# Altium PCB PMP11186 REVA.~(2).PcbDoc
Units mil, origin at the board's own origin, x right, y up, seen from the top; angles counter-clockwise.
Board outline 4950 x 3450 mil, 2 copper layers (Top Layer, Bottom Layer), stack 62 mil thick; 91 components, 38 nets, 225 pads, 56 vias.
Unrouted connection lines stored in the file: 161.
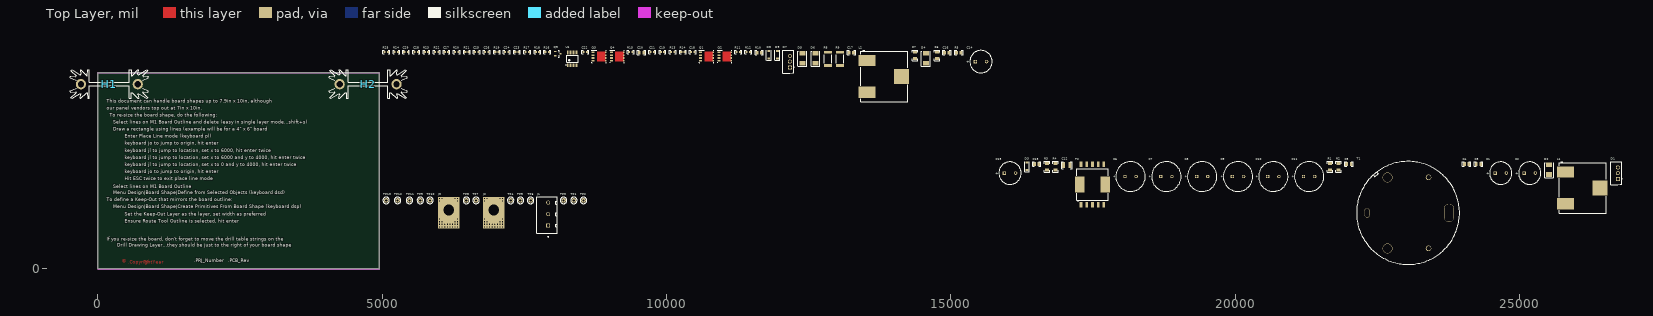
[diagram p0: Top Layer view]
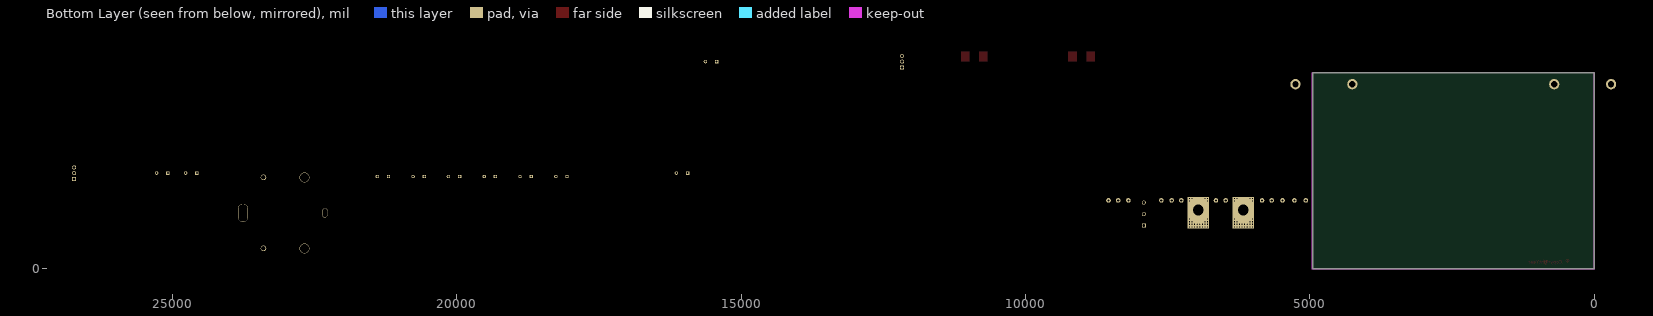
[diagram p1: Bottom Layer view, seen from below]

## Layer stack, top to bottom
Top Solder: solder mask 0.4, Solder Resist, Dk 3.5
Top Layer: signal copper 1.4
Dielectric1: core 59.2, FR-4, Dk 4.8
Bottom Layer: signal copper 1.4
Bottom Solder: solder mask 0.4, Solder Resist, Dk 3.5

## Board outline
0,0 4950,0 4950,3450 0,3450

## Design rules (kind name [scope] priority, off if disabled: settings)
AcuteAngle [All] p1: minimum=4.50000000000000E+0001 checktracksonly=FALSE
AssemblyTestPointUsage [All] p1: valid=2
Clearance Clearance_Keepouts [((IsTrack Or IsArc) And Not InPoly) And IsFree and IsKeepOut vs ((IsTrack Or IsArc) And Not InPoly) And IsFree and IsKeepOut] p1: gap=0
Clearance Clearance_BoardEdge_MountingHoles [OnCopper and InComponentClass('Mounting Holes') vs IsKeepOut] p2: gap=40
Clearance Clearance_BoardEdge_Poly [OnCopper and InPoly vs IsKeepOut] p3: gap=25
Clearance Clearance_BoardEdge [OnCopper and Not InComponentClass('Logo') and not InComponentClass('FiducialMark') and not InRegion(1000,500,4000,800) and Not IsKeepout vs IsKeepOut] p4: gap=75
Clearance Clearance_Poly [InPolygon] p5: gap=25
Clearance [All] p6: gap=7.87
ComponentClearance ComponentClearance_MountingHoles_FiducialMarks [InComponentClass('Mounting Holes') vs InComponentClass('FiducialMark')] p1: gap=50 collisioncheckmode=3 verticalgap=10 showdistances=FALSE
ComponentClearance ComponentClearance_Shunt [InComponentClass('Header') vs InComponentClass('Shunt')] p2: gap=0 collisioncheckmode=3 verticalgap=0 showdistances=FALSE
ComponentClearance ComponentClearance_Logo [InComponentClass('Logo')] p3: gap=50 collisioncheckmode=3 verticalgap=10 showdistances=FALSE
ComponentClearance ComponentClearance_ScrewToNut [(HasFootprint('NY PMS 440 0025 PH')) vs (HasFootprint('Keystone_1902C'))] p4: gap=5 collisioncheckmode=3 verticalgap=10 showdistances=FALSE
ComponentClearance ComponentClearance_MountingHoles [InComponentClass('Mounting Holes')] p5: gap=250 collisioncheckmode=3 verticalgap=100000 showdistances=FALSE
ComponentClearance ComponentClearance_SmallPassives [HasFootprint('0201*') or HasFootprint('0402*') or HasFootprint('0508') or HasFootprint('0603*') or HasFootprint('0612') or HasFootprint('0805*') or HasFootprint('0815*') or HasFootprint('0830*') or HasFootprint('1206*') or HasFootprint('1210*') or HasFootprint('1808*') or HasFootprint('1812*') or HasFootprint('1825*') or HasFootprint('2010*') or HasFootprint('2220*') or HasFootprint('2225*') or HasFootprint('2512*') or HasFootprint('2728*') or HasFootprint('3518*') vs HasFootprint('0201*') or HasFootprint('0402*') or HasFootprint('0508') or HasFootprint('0603*') or HasFootprint('0612') or HasFootprint('0805*') or HasFootprint('0815*') or HasFootprint('0830*') or HasFootprint('1206*') or HasFootprint('1210*') or HasFootprint('1808*') or HasFootprint('1812*') or HasFootprint('1825*') or HasFootprint('2010*') or HasFootprint('2220*') or HasFootprint('2225*') or HasFootprint('2512*') or HasFootprint('2728*') or HasFootprint('3518*')] p6: gap=20 collisioncheckmode=3 verticalgap=10 showdistances=FALSE
ComponentClearance ComponentClearance_THtoSMT [IsThruComponent vs IsSMTComponent] p7: gap=100 collisioncheckmode=3 verticalgap=30 showdistances=FALSE
ComponentClearance ComponentClearance_THtoTH [IsThruComponent vs IsThruComponent] p8: gap=118.11 collisioncheckmode=3 verticalgap=30 showdistances=FALSE
ComponentClearance [All] p9: gap=40 collisioncheckmode=3 verticalgap=10 showdistances=FALSE
DiffPairsRouting [All] p1: maxlimit=100 minlimit=10 mostfreqgap=10 toplayer_minwidth=15 toplayer_maxwidth=15 toplayer_prefwidth=15 bottomlayer_minwidth=15 bottomlayer_maxwidth=15 bottomlayer_prefwidth=15 maxuncoupledlength=1000
FabricationTestPointUsage TestPointUsage [All] p1: valid=2 allowmultiple=FALSE
FabricationTestpoint Testpoint [All] p1: side=3 testpointundercomponent=TRUE minsize=40 maxsize=100 preferedsize=60 minholesize=0 maxholesize=40 preferedholesize=32 testpointgrid=1 allowsidetop=TRUE allowsidebottom=TRUE usegrid=TRUE gridtolerance=0.01
FanoutControl Fanout_LCC [IsLCC] p1: bgadir=Out bgaviamode=Centered fanoutstyle=Auto fanoutdirection=Alternating viagrid=1 // Fanout_LCC (Default Rule)
FanoutControl Fanout_BGA [IsBGA] p2: bgadir=Out bgaviamode=Centered fanoutstyle=Auto fanoutdirection=Alternating viagrid=1 // Fanout_BGA (Default Rule)
FanoutControl Fanout_Default [All] p4: bgadir=Out bgaviamode=Centered fanoutstyle=Auto fanoutdirection=Alternating viagrid=1 // Fanout_Default (Default Rule)
FanoutControl Fanout_Small [(CompPinCount < 5)] p5: bgadir=Out bgaviamode=Centered fanoutstyle=Auto fanoutdirection=OutThenIn viagrid=1 // Fanout_Small (Default Rule)
HoleSize [All] p1: absolutevalues=TRUE maxlimit=251 minlimit=8 maxpercent=80.000 minpercent=20.000
MinimumAnnularRing MinimumAnnularRing_ThermalPadVias [IsVia and InAnyComponent] p1: minimumring=5.91
MinimumAnnularRing [All] p2: minimumring=9
MinimumSolderMaskSliver MinimumSolderMaskSliver_Logo [InComponentClass('Logo') vs InComponentClass('Logo')] p1: minsoldermaskwidth=0.7
MinimumSolderMaskSliver [All] p2: minsoldermaskwidth=3.94
PlaneConnect [All] p1: planeconnectstyle=Relief reliefexpansion=10 reliefentries=4 reliefconductorwidth=10 reliefairgap=10
PolygonConnect [All] p1: connectstyle=Relief reliefconductorwidth=10 reliefentries=4 polygonreliefangle="90 Angle" airgapwidth=10
RoutingVias ThermalPadVias [IsVia and InAnyComponent] p1: holewidth=7.87 width=19.68 viastyle="Through Hole" minholewidth=7.87 minwidth=19.68 maxholewidth=12.99 maxwidth=23.62
RoutingVias [All] p2: holewidth=16 width=34 viastyle="Through Hole" minholewidth=7.87 minwidth=26 maxholewidth=40 maxwidth=65
SilkToBoardRegionClearance [Not ((IsComment or IsDesignator) And (Hide <> 'False')) and not InRegion(1000,500,4000,800)] p1:
SilkToSilkClearance SilkToSilkClearance_Pb-FreeLogo [(HasFootprint('Pb-Free_Overlay_Medium') OR HasFootprint('Pb-Free_Overlay_Small')) vs (HasFootprint('Pb-Free_Overlay_Medium') OR HasFootprint('Pb-Free_Overlay_Small'))] p1: silktosilkclearance=0
SilkToSilkClearance [All] p2: silktosilkclearance=5
SilkToSolderMaskClearance "Silk to Solder Mask Opening" [All] p1: minsilkscreentomaskgap=1 clearancetoexposedcopper=FALSE
SolderMaskExpansion [All] p1: expansion=1.97
UnpouredPolygon [All] p1: allowunpoured=FALSE
Width [All] p1: maxlimit=100 minlimit=6 preferedwidth=10 checkconnectedcopper=TRUE
14 further rules are at their usual default settings.

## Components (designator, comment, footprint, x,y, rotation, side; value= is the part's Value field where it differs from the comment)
C1 "35ZL470MEFC10X20" CAPPR5-10X20 24668,1686 r0 top
C2 "35ZL470MEFC10X20" CAPPR5-10X20 25178,1686 r0 top
C3 "GRM21BR71H105KA12L" 0805_HV 24278,1846 r0 top
C4 "GRM21A5C2E101JW01D" 0805_HV 24068,1846 r0 top
C5 "C2012X7R2A103M" 0805_HV 21998,1846 r0 top
C6 "25ZLH2700M12.5X35" ZLH_1250x2500 18158,1626 r0 top
C7 "25ZLH2700M12.5X35" ZLH_1250x2500 18788,1626 r0 top
C8 "25ZLH2700M12.5X35" ZLH_1250x2500 19418,1626 r0 top
C9 "25ZLH2700M12.5X35" ZLH_1250x2500 20048,1626 r0 top
C10 "25ZLH2700M12.5X35" ZLH_1250x2500 20668,1626 r0 top
C11 "25ZLH2700M12.5X35" ZLH_1250x2500 21298,1626 r0 top
C12 "C3225X7R1E106M" 1210 17038,1826 r0 top
C13 "C2012X7R2A103M" 0805_HV 16508,1846 r0 top
C14 "35ZL470MEFC10X20" CAPPR5-10X20 15528,3646 r0 top
C15 "35ZL470MEFC10X20" CAPPR5-10X20 16038,1686 r0 top
C16 "GRM21BR71H105KA12L" 0805_HV 14928,3806 r0 top
C17 "C2012X7R2A103M" 0805_HV 13248,3806 r0 top
C18 "C1608C0G1H152J" 0603 10458,3816 r0 top
C19 "C1608C0G1H101J" 0603 9928,3816 r0 top
C20 "C2012X7R1E105K" 0805_HV 9558,3806 r0 top
C21 "" 0603 9748,3816 r0 top
C22 "C1608X7R1C105K" 0603 8568,3816 r0 top
C23 "C1608X7R1H473K" 0603 7368,3816 r0 top
C24 "C1608C0G1H150J" 0603 7188,3816 r0 top
C25 "C1608X7R1C105K" 0603 6658,3816 r0 top
C26 "C1608X7R1H103K" 0603 6838,3816 r0 top
C27 "" 0603 6128,3816 r0 top
C28 "C1608X7R1C105K" 0603 5598,3816 r0 top
C29 "C1608C0G1H101J" 0603 5418,3816 r0 top
D1 "FML22S" ITO-220AB 26728,1686 r90 top
D2 "MURS120-13-F" SMB 25518,1746 r90 top
D3 "MMSD4148T1G" SOD-123 16338,1806 r90 top
D4 "MURS120-13-F" SMB 14558,3706 r90 top
D5 "MURS120-13-F" SMB 12388,3706 r90 top
D6 "MURS120-13-F" SMB 12618,3706 r90 top
D7 "FML22R" ITO-220AB 12168,3646 r90 top
D8 "BAT54T1G" SOD-123 11798,3766 r90 top
D9 "BAT54T1G" SOD-123 11948,3766 r90 top
H1 "513201B02500G" HSINK_513201B02500 200,3250 r0 top locked
H2 "513201B02500G" HSINK_513201B02500 4750,3250 r0 top locked
J1 "OSTTA034163" On-Shore_OSTTA034163 7898,946 r90 top
J2 "CB35-36-CY" CB35-36-CY 6958,1036 r90 top
J3 "CB35-36-CY" CB35-36-CY 6168,1036 r90 top
L1 "B82559A0353A020" B82559_1420 26108,1426 r0 top
L2 "B82559A0353A020" B82559_1420 13828,3386 r0 top
Q1 "DNP" TRANS_NexFET_Q5B 10708,3736 r0 top
Q2 "DNP" TRANS_NexFET_Q5B 11028,3736 r0 top
Q3 "CSD18540Q5B" TRANS_NexFET_Q5B 8818,3736 r0 top
Q4 "CSD18540Q5B" TRANS_NexFET_Q5B 9138,3736 r0 top
Q5 "2N7002P,215" SOT-23 8088,3786 r0 top
R1 "" 1206 21668,1796 r90 top
R2 "CRCW120649K9FKEA" 1206 21818,1796 r90 top
R3 "" 1206 16688,1796 r90 top
R4 "CRCW120649K9FKEA" 1206 16838,1796 r90 top
R5 "CRCW08051K00FKEA" 0805_HV 15138,3806 r0 top
R6 "CRCW1206100RFKEA" 1206 14758,3756 r90 top
R7 "CSR1206FKR750" 1206 14368,3756 r90 top
R8 "" 2512 12838,3696 r90 top
R9 "CRCW251210K0JNEG" 2512 13048,3696 r90 top
R10 "ERJ-6GEYJ4R7V" 0805_HV 11628,3806 r0 top
R11 "" 0603 11258,3816 r0 top
R12 "CRCW06031K00FKEA" 0603 11438,3816 r0 top
R13 "CRCW06031R00FKEA" 0603 10108,3816 r0 top
R14 "CRCW06031R00FKEA" 0603 10288,3816 r0 top
R15 "CRCW0603130KFKEA" 0603 9368,3816 r0 top
R16 "CRCW0603200KFKEA" 0603 7898,3816 r0 top
R17 "CRCW060310K0FKEA" 0603 7548,3816 r0 top
R18 "CRCW060321K0FKEA" 0603 7728,3816 r0 top
R19 "CRCW0603100KFKEA" 0603 7018,3816 r0 top
R20 "CRCW060347K5FKEA" 0603 6308,3816 r0 top
R21 "CRCW060349R9FKEA" 0603 6488,3816 r0 top
R22 "" 0603 5958,3816 r0 top
R23 "CRCW06032K49FKEA" 0603 5778,3816 r0 top
R24 "CRCW060349K9FKEA" 0603 5248,3816 r0 top
R25 "CRCW060329K4FKEA" 0603 5068,3816 r0 top
T1 "G154027ALF" GCI_G154027ALF 23038,986 r0 top
T2 "G154028ALF" GCI_G154028ALF 17488,1486 r90 top
TP1 "5000" Keystone5000 8368,1206 r0 top
TP2 "5000" Keystone5000 8538,1206 r0 top
TP3 "5000" Keystone5000 8188,1206 r0 top
TP4 "5000" Keystone5000 7258,1206 r0 top
TP5 "5001" Keystone5001 7428,1206 r0 top
TP6 "5001" Keystone5001 7608,1206 r0 top
TP7 "5000" Keystone5000 6648,1206 r0 top
TP8 "5001" Keystone5001 6478,1206 r0 top
TP9 "5000" Keystone5000 5668,1206 r0 top
TP10 "5000" Keystone5000 5838,1206 r0 top
TP11 "5000" Keystone5000 5478,1206 r0 top
TP12 "5000" Keystone5000 5268,1206 r0 top
TP13 "5000" Keystone5000 5068,1206 r0 top
U1 "LM25037QMT" MTC16_N 8348,3696 r90 top

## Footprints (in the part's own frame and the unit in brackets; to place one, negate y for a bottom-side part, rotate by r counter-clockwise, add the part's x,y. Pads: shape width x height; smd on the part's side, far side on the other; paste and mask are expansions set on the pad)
0603 [mm] "0603 from SM-752 data"
  rect 1x0.95 smd: 1(-0.8,0) 2(0.8,0)
  silkscreen extent -1.52,-0.69 1.52,0.69, body extent -0.87,-0.47 0.87,0.47, height 0.85
0805_HV [mil] "0805 with 30mil clearance between pads"
  rect 50x63 smd: 1(-40,0) 2(40,0)
  silkscreen extent -74,-40 74,40, body extent -43,-29 43,29, height 57
1206 [mm] "1206 from SM-752 data"
  rect 1.3x1.85 smd: 1(-1.45,0) 2(1.45,0)
  silkscreen extent -2.4,-1.21 2.4,1.21, body extent -1.7,-0.9 1.7,0.9, height 1.35
1210 [mm] "1210 from SM-752 data"
  rect 1.3x2.7 smd: 1(-1.45,0) 2(1.45,0)
  silkscreen extent -2.32,-1.57 2.32,1.57, body extent -1.7,-1.35 1.7,1.35, height 1.35
2512 [mm] "Chip Resistor, Body 6.3x3.2mm, IPC Medium Density"
  rect 1.3x3.4 smd: 1(-2.95,0) 2(2.95,0)
  silkscreen extent -1.9,-1.6 1.9,1.6, body extent -3.22,-1.67 3.22,1.67, height 0.71
B82559_1420 [mm] "SMD, 3-Leads, Body 21.5x21mm"
  rect 7.6x5 smd: 1(-7.675,7.1) 2(-7.675,-7.1)
  rect 6.7x6.8 smd: 3(7.675,0)
  silkscreen extent -10.5,-11.25 10.5,11.7, body extent -11,-11.25 11,11.25, height 14.2
CAPPR5-10X20 [mm] "Capacitor, Electrolytic, Radial; Body 10 x 20 mm (Dia.xH typ); Pin Spacing 5 mm (typ)"
  rect 1.5x1.5 hole 0.9: 1(-2.5,0)
  round 1.5 hole 0.9: 2(2.5,0)
  silkscreen extent -5,-5 5,5, body extent -5.01,-5.01 5.01,5.01, height 22
CB35-36-CY [mil] "Terminal 50A Lug"
  rect 550x380 hole 188 copper offset -45,0 paste-190: 1(0,0)
  body extent -960,-189 230,191, height 614
GCI_G154027ALF [mm] "TH, 6-Leads, Dia 46mm"
  round 4.4 hole 3.9: 1(-9.15,15.848) 3(-9.15,-15.848)
  oval 2.5x4.1 hole 2 slot 3.6 at 90 deg: 2(-18.3,0)
  round 2.5 hole 2: 4(9.15,-15.848) 6(9.15,15.848)
  oval 4.5x8.1 hole 4 slot 7.6 at 90 deg: 5(18.3,0)
  silkscreen extent -23,-23 23,23, body extent -23.01,-23.01 23.01,23.01, height 28
GCI_G154028ALF [mm] "SMD, 12-Leads, Body 14.2x20mm, Pitch 2.54mm"
  rect 2.35x1.2 smd: 1(-9.025,5.08) 2(-9.025,2.54) 3(-9.025,0) 4(-9.025,-2.54) 5(-9.025,-5.08) 6(9.025,-5.08) 7(9.025,-2.54) 8(9.025,0) 9(9.025,2.54) 10(9.025,5.08)
  rect 7.2x4.25 smd: 11(0,5.625) 12(0,-5.625)
  silkscreen extent -7.5,-7.1 7.1,7.1, body extent -10,-7.25 10,7.25, height 10.52
HSINK_513201B02500 [mil] "Aavid"
  round 180 hole 110.24: 1(-500,0) 2(500,0)
  silkscreen extent -685,-250 685,250, body extent -685,-250 685,250, height 2000
ITO-220AB [mm] "TH, 3-Leads, Body 10.11x15.87mm, Pitch 2.54mm"
  rect 1.8x1.8 hole 1.3: 1(-2.54,0)
  round 1.8 hole 1.3: 2(0,0) 3(2.54,0)
  silkscreen extent -5.16,-1.9 5.15,3.24, body extent -5.16,-1.66 5.16,3.24, height 19.67
Keystone5000 [mil] "For Keystone 500x miniature loop terminals"
  round 80 hole 40: 1(0,0)
  silkscreen extent -58,-58 58,58, body extent -49,-49 49,49, height 182
Keystone5001 [mil] "For Keystone 500x miniature loop terminals"
  round 80 hole 40: 1(0,0)
  silkscreen extent -58,-58 58,58, body extent -49,-49 49,49, height 182
MTC16_N [mm] "TSOP, 16-Leads, Body 5x4.4mm, Pitch 0.65mm, IPC Medium Density"
  oval 1.7x0.35 smd: 1(-2.85,2.275) 2(-2.85,1.625) 3(-2.85,0.975) 4(-2.85,0.325) 5(-2.85,-0.325) 6(-2.85,-0.975) 7(-2.85,-1.625) 8(-2.85,-2.275) 9(2.85,-2.275) 10(2.85,-1.625) 11(2.85,-0.975) 12(2.85,-0.325) 13(2.85,0.325) 14(2.85,0.975) 15(2.85,1.625) 16(2.85,2.275)
  silkscreen extent -2.97,-2.55 1.6,3.12, body extent -2.25,-2.55 2.25,2.55, height 1.1
On-Shore_OSTTA034163 [mm] "TERM BLOCK 3x1, 5.08mm, TH"
  rect 1.8x1.8 hole 1.3: 1(-4.58,-0.5)
  round 1.8 hole 1.3 paste+0: 2(0.5,-0.5) 3(5.58,-0.5)
  silkscreen extent -9.73,-4.55 8.17,4.55, body extent -8.22,-4.6 8.22,4.6, height 13
SMB [mil] "Molded Diode, 2-Leads, Body 5.4x3.6mm, IPC Medium Density, based on OnSemi component dimensions"
  rect 85x107.99 smd: 1(-87.01,0) 2(87.01,0)
  silkscreen extent -155,-82 125,82, body extent -106,-71 106,71, height 91
SOD-123 [mm] "On Semi recommended land pattern"
  rect 0.915x1.22 smd: 1(-1.637,0) 2(1.637,0)
  silkscreen extent -2.74,-1.17 2.03,1.17, body extent -1.93,-0.9 1.93,0.9, height 1.35
SOT-23 [mm] "SOT23, 3-Leads, Body 2.9x1.3mm, Pitch 0.95mm, Lead Span 2.5mm, IPC Medium Density"
  rrect50% 1x0.6 smd: 1(-1.2,0.95) 2(-1.2,-0.95) 3(1.2,0)
  silkscreen extent -1.63,-1.5 0.7,1.5, body extent -1.16,-1.45 1.21,1.45, height 1
TRANS_NexFET_Q5B [mm] "TI recommended land pattern (nominal) November 2012"
  rect 1.372x0.71 smd paste-0.4: 1(-2.776,1.905) 2(-2.776,0.635) 3(-2.776,-0.635) 4(-2.776,-1.905)
  rect 0.59x0.71 smd paste-0.3: 5(2.776,-1.905) 6(2.776,-0.635) 7(2.776,0.635) 8(2.776,1.905)
  Top Layer region: -1.106,-2.26 2.744,-2.26 2.744,2.26 -1.106,2.26
  silkscreen extent -3.38,-2.7 3,2.7, body extent -3.23,-2.55 2.87,2.55, height 1.06
ZLH_1250x2500 [mm] "Rubycon"
  rect 1.5x1.5 hole 0.85: 1(-2.5,0)
  round 1.5 hole 0.85: 2(2.5,0)
  silkscreen extent -6.6,-6.6 6.6,6.6, body extent -6.45,-6.49 6.49,6.49, height 26.51

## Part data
C1 C2 C14 C15: "CAP, AL, 470 µF, 35 V, 0.023 Ohms, 1.82A, TH"
C3 C16: "CAP, CERM, 1uF, 50V, +/-10%, X7R, 0805"
C4: "CAP, CERM, 100 pF, 250 V, +/- 5%, C0G/NP0, 0805"
C5 C13 C17: "CAP, CERM, 0.01 µF, 100 V, +/- 20%, X7R, 0805"
C6 C7 C8 C9 C10 C11: library part 63ZLH470M12.5X25, "CAP, AL, 2700 µF, 25 V, 0.016 ohm, 4.12A, TH"
C12: "CAP, CERM, 10 µF, 25 V, +/- 20%, X7R, 1210"
C18: "CAP, CERM, 1500 pF, 50 V, +/- 5%, C0G/NP0, 0603"
C19 C29: "CAP, CERM, 100 pF, 50 V, +/- 5%, C0G/NP0, 0603"
C20: "CAP, CERM, 1 µF, 25 V, +/- 10%, X7R, 0805"
C21 C27: library part C1608C0G1H271J, "CAP, DNP, 0603"
C22 C25 C28: "CAP, CERM, 1 µF, 16 V, +/- 10%, X7R, 0603"
C23: "CAP, CERM, 0.047 µF, 50 V, +/- 10%, X7R, 0603"
C24: "CAP, CERM, 15 pF, 50 V, +/- 5%, C0G/NP0, 0603"
C26: "CAP, CERM, 0.01 µF, 50 V, +/- 10%, X7R, 0603"
D1 D7: "Diode, Ultrafast, 200 V, 10 A, TH"
D2 D4 D5 D6: "Diode, Superfast Rectifier, 200 V, 1 A, SMB"
D3: "Diode, Switching, 100 V, 0.2 A, SOD-123"
D8 D9: "Diode, Schottky, 30V, 0.2A, SOD-123"
H1 H2: "HEATSINK TO-218/TO-247 W/PINS 2\""
J1: "Terminal Block, 3x1, 5.08 mm, TH"
J2 J3: "Terminal 50A Lug"
L1 L2: "Inductor, Wirewound, Ferrite, 35 µH, 9.3 A, 0.007 ohm, SMD"
Q1 Q2: library part CSD18540Q5B, "MOSFET, DNP, SON 5x6mm"
Q3 Q4: "MOSFET, N-CH, 60 V, 28 A, SON 5x6mm"
Q5: "MOSFET, N-CH, 60 V, 0.36 A, SOT-23"
R1 R3: library part CRCW120649K9FKEA, "RES, DNP, 1206"
R2 R4: "RES, 49.9 k, 1%, 0.25 W, 1206"
R5: "RES, 1.00 k, 1%, 0.125 W, 0805"
R6: "RES, 100 ohm, 1%, 0.25W, 1206"
R7: "RES, 0.75, 1%, 0.5 W, 1206"
R8: library part CRCW251210K0JNEG, "RES, DNP, 2512"
R9: "RES, 10 k, 5%, 1 W, 2512"
R10: "RES, 4.7, 5%, 0.125 W, 0805"
R11 R22: library part CRCW060332K4FKEA, "RES, DNP, 0603"
R12: "RES, 1.00 k, 1%, 0.1 W, 0603"
R13 R14: "RES, 1.00 ohm, 1%, 0.1W, 0603"
R15: "RES, 130 k, 1%, 0.1 W, 0603"
R16: "RES, 200 k, 1%, 0.1 W, 0603"
R17: "RES, 10.0k ohm, 1%, 0.1W, 0603"
R18: "RES, 21.0 k, 1%, 0.1 W, 0603"
R19: "RES, 100 k, 1%, 0.1 W, 0603"
R20: "RES, 47.5 k, 1%, 0.1 W, 0603"
R21: "RES, 49.9, 1%, 0.1 W, 0603"
R23: "RES, 2.49k ohm, 1%, 0.1W, 0603"
R24: "RES, 49.9 k, 1%, 0.1 W, 0603"
R25: "RES, 29.4 k, 1%, 0.1 W, 0603"
T1: "Transformer, 50 uH, TH"
T2: "Transformer, 22.4 mH, SMT"
TP1 TP2 TP3 TP4 TP7 TP9 TP10 TP11 TP12 TP13: "Test Point, Miniature, Red, TH"
TP5 TP6 TP8: "Test Point, Miniature, Black, TH"
U1: "Dual-Mode PWM Controller With Alternating Outputs, Automotive Grade, 16-pin TSSOP"

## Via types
v1: diameter 32, hole 16, Top Layer to Bottom Layer, 56 vias

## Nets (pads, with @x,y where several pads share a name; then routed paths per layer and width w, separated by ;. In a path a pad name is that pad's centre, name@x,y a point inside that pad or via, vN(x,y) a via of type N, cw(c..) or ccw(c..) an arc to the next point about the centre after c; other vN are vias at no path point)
GND: C1.2 C2.2 C3.2 C5.2 C6.2 C7.2 C8.2 C9.2 C10.2 C11.2 C12.2 C13.1 C14.1 C15.1 C16.1 C19.1 C20.2 C21.1 C22.1 C25.2 C26.2 C28.2 J1.2 J3.1 Q1.1 Q1.2 Q1.3 Q2.1 Q2.2 Q2.3 Q3.1 Q3.2 Q3.3 Q4.1 Q4.2 Q4.3 Q5.2 R1.1 R2.1 R3.2 R4.2 R5.2 R7.1 R17.1 R18.1 R23.1 R24.1 R25.1 T1.2 T2.4 TP5.1 TP6.1 TP8.1 U1.6 U1.11
  other v1: 6008,741 6053,741 6098,741 6143,741 6188,741 6233,741 6278,741 6323,741 6008,786 6053,786 6098,786 6143,786 6188,786 6233,786 6278,786 6323,786 6008,831 6053,831 6278,831 6323,831 6008,876 6323,876 6008,1196 6323,1196 6008,1241 6053,1241 6278,1241 6323,1241
NetC4_1: C4.1 D1.2 D2.2 L1.1 TP1.1
NetC4_2: C4.2 R6.2
NetC5_1: C5.1 D2.1 R1.2 R2.2
NetC6_1: C6.1 C7.1 C8.1 C9.1 C10.1 C11.1 C12.1 C17.1 J2.1 R8.2 R9.2 R10.2 R11.1 R15.2 T2.11 TP4.1
  other v1: 6798,741 6843,741 6888,741 6933,741 6978,741 7023,741 7068,741 7113,741 6798,786 6843,786 6888,786 6933,786 6978,786 7023,786 7068,786 7113,786 6798,831 6843,831 7068,831 7113,831 6798,876 7113,876 6798,1196 7113,1196 6798,1241 6843,1241 7068,1241 7113,1241
NetC13_2: C13.2 D4.2 R3.1 R4.1
NetC14_2: C14.2 C15.2 C16.2 J1.3 L2.2 TP10.1
NetC17_2: C17.2 D5.1 D6.1 R8.1 R9.1
NetC18_1: C18.1 C21.2 R11.2 R16.2 U1.1
NetC18_2: C18.2 C19.2 R12.1 U1.8
NetC20_1: C20.1 R10.1 U1.16
NetC22_2: C22.2 R16.1 U1.15
NetC23_1: C23.1 R19.2
NetC23_2: C23.2 C24.1 U1.3
NetC24_2: C24.2 R19.1 R20.1 R22.1 R23.2 U1.4
NetC25_1: C25.1 U1.10
NetC26_1: C26.1 U1.9
NetC27_1: C27.1 R22.2
NetC27_2: C27.2 R20.2 R21.2 TP12.1
NetC28_1: C28.1 U1.14
NetC29_1: C29.1 TP13.1
NetC29_2: C29.2 R25.2 U1.7
NetD1_1: D1.1 D7.1 T1.4
NetD1_3: D1.3 D7.3 T1.6
NetD3_1: D3.1 R7.2 R12.2
NetD3_2: D3.2 R5.1 T2.2
NetD4_1: D4.1 D7.2 L2.1 R6.1 TP9.1
NetD5_2: D5.2 Q1.5 Q1.6 Q1.7 Q1.8 Q3.5 Q3.6 Q3.7 Q3.8 T1.1 TP3.1
NetD6_2: D6.2 Q2.5 Q2.6 Q2.7 Q2.8 Q4.5 Q4.6 Q4.7 Q4.8 T1.3 TP7.1
NetD8_1: D8.1 R13.1 U1.13
NetD8_2: D8.2 Q1.4 Q3.4 R13.2
NetD9_1: D9.1 R14.1 U1.12
NetD9_2: D9.2 Q2.4 Q4.4 R14.2
NetQ5_1: Q5.1 R17.2 TP11.1
NetQ5_3: Q5.3 R15.1 R18.2 U1.2
NetR24_2: R24.2 U1.5
NetT1_5: T1.5 T2.12
VOUT: C1.1 C2.1 C3.1 J1.1 L1.2 R21.1 TP2.1
pads on no net: H1.1 H1.2 H2.1 H2.2 L1.3 L2.3 T2.1 T2.3 T2.5 T2.6 T2.7 T2.8 T2.9 T2.10

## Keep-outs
Keep-Out Layer:
  lines w10: -5,0 ccw(c0,0) 0,-5 ; -5,0 ccw(c0,0) 0,-5 ; -5,0 -5,3450 ; -5,3450 cw(c0,3450) 0,3455 ; -5,3450 cw(c0,3450) 0,3455 ; 0,-5 4950,-5 ; 0,3455 4950,3455 ; 4950,-5 ccw(c4950,0) 4955,0 ; 4950,-5 ccw(c4950,0) 4955,0 ; 4950,3455 cw(c4950,3450) 4955,3450 ; 4950,3455 cw(c4950,3450) 4955,3450 ; 4955,0 4955,3450
  text ".Layer_Name" at 577,-858.49 h60

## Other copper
Top Layer:
  text ".CopyrightYear" at 532,90 h60
  text "TI" at 808,90 h60
  text "©" at 415,86.48 h105
  text ".Layer_Name" at 577,-858.49 h60
Bottom Layer:
  text ".Layer_Name" at 577,-858.49 h60

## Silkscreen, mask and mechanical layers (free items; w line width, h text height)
Top Overlay:
  text "This document can handle board shapes up to 7.9in x 10in, although" at 150,2925 h60
  text "our panel vendors top out at 7in x 10in." at 150,2800.94 h60
  text "To re-size the board shape, do the following:" at 205,2676.88 h60
  text "Select lines on M1 Board Outline and delete (easy in single layer mode...shift+s)" at 265,2552.82 h60
  text "Draw a rectangle using lines (example will be for a 4\" x 6\" board" at 265,2428.76 h60
  text "Enter Place Line mode (keyboard pl)" at 475,2304.71 h60
  text "keyboard jo to jump to origin, hit enter" at 475,2180.65 h60
  text "keyboard jl to jump to location, set x to 6000, hit enter twice" at 475,2056.59 h60
  text "keyboard jl to jump to location, set x to 6000 and y to 4000, hit enter twice" at 475,1932.53 h60
  text "keyboard jl to jump to location, set x to 0 and y to 4000, hit enter twice" at 475,1808.47 h60
  text "keyboard jo to jump to origin, hit enter" at 475,1684.41 h60
  text "Hit ESC twice to exit place line mode" at 475,1560.35 h60
  text "Select lines on M1 Board Outline" at 265,1416.3 h60
  text "Menu Design|Board Shape|Define from Selected Objects (keyboard dsd)" at 265,1312.24 h60
  text "To define a Keep-Out that mirrors the board outline:" at 150,1188.18 h60
  text "Menu Design|Board Shape|Create Primitives From Board Shape (keyboard dsp)" at 265,1064.12 h60
  text "Set the Keep-Out Layer as the layer, set width as preferred" at 475,940.06 h60
  text "Ensure Route Tool Outline is selected, hit enter" at 475,816 h60
  text "If you re-size the board, don't forget to move the drill table strings on the" at 150,493 h60
  text "Drill Drawing Layer...they should be just to the right of your board shape" at 343,387 h60
  text ".PRJ_Number" at 1690,120 h60
  text ".PCB_Rev" at 2290,120 h60
  text ".Layer_Name" at 577,-858.49 h60
Bottom Overlay:
  text ".Layer_Name" at 577,-858.49 h60
Top Paste:
  text ".Layer_Name" at 577,-858.49 h60
Bottom Paste:
  text ".Layer_Name" at 577,-858.49 h60
Top Solder:
  text ".Layer_Name" at 577,-858.49 h60
  text ".Layer_Name" at 577,-858.49 h60
Bottom Solder:
  text ".Layer_Name" at 577,-858.49 h60
Drill Guide:
  text ".Layer_Name" at 577,-858.49 h60
M1 Board Outline:
  the board outline again, w10
  text ".Layer_Name" at 577,-858.49 h60
M2 Board Dimensions:
  rectangle: 125,-400 500,-275
  rectangle: 0,-275 125,-150
  lines w7: 0,-275 1000,-275 ; 125,-400 125,-150 ; 250,-400 250,-150 ; 500,-400 500,-150 ; 750,-400 750,-150 ; 0,-400 0,-150 1000,-150 1000,-400 0,-400
  text ".Layer_Name" at 577,-858.49 h60
M3 3D STEP Top:
  text ".Layer_Name" at 577,-858.49 h60
M4 3D STEP Bottom:
  text ".Layer_Name" at 577,-858.49 h60
M5 Assembly Top:
  lines w10: -292,-930.17 6308,-930.17 ; -292,-726.83 6310,-726.83 ; -292,-523.5 -292,-1133.5 3713,-1133.5 6310,-1133.5 6310,-523.5 -291.5,-523.5 -291.5,-1133.5 1284,-1133.5 ; 2173,-1133.5 2173,-523.5 ; 3440,-726.83 3440,-523.5 ; 4280,-726.83 4280,-523.5 ; 4902,-1140 4902,-937.17
  text "COMPONENTS MARKED 'DNP' SHOULD NOT BE POPULATED." at 1153.5,-318.5 h60
  text "ASSEMBLY VARIANT:" at 1153,-434 h60
  text ".VariantName" at 2189,-434 h60
  text "PCB VIEWED FROM TOP SIDE" at -228.5,-655.67 h60
  text "BOARD #:" at 2248,-655.67 h60
  text ".PRJ_Number" at 2793.5,-655.67 h60
  text "REV:" at 3638,-655.67 h60
  text ".PCB_Rev" at 3929.5,-655.67 h60
  text "SVN REV:" at 4476,-655.67 h60
  text ".VersionControl_RevNumber" at 4982,-655.67 h60
  text "TID #:" at 2248,-859 h60
  text ".TID" at 2793.5,-859 h60
  text "PLOT NAME =" at -228.5,-1064.34 h60
  text ".plot_File_Name" at 577,-1064.34 h60
  text "GENERATED    :" at 2250,-1064.34 h60
  text ".Print_Date" at 3119.5,-1064.34 h60
  text ".Print_Time" at 3848.5,-1064.34 h60
  text "TEXAS INSTRUMENTS" at 5113,-1064.34 h60
M6 Assembly Bottom:
  lines w10: -292.5,-727.33 6309.5,-727.33 ; -290.5,-930.67 6309.5,-930.67 ; 1115.5,-1140.5 1115.5,-937.67 ; 1737.5,-727.33 1737.5,-524 ; 2577.5,-727.33 2577.5,-524 ; 3844.5,-1134 3844.5,-524 ; 4733.5,-1134 6309,-1134 6309,-524 -292.5,-524 -292.5,-1134 2304.5,-1134 6309.5,-1134 6309.5,-524
  text "COMPONENTS MARKED 'DNP' SHOULD NOT BE POPULATED." at 6102,-318 h60
  text ".VariantName" at 5058,-434 h60
  text "ASSEMBLY VARIANT:" at 6097,-434 h60
  text ".VersionControl_RevNumber" at 1035.5,-656.17 h60
  text "SVN REV:" at 1541.5,-656.17 h60
  text ".PCB_Rev" at 2088,-656.17 h60
  text "REV:" at 2379.5,-656.17 h60
  text ".PRJ_Number" at 3224,-656.17 h60
  text "BOARD #:" at 3769.5,-656.17 h60
  text "PCB VIEWED FROM BOTTOM SIDE" at 6246,-656.17 h60
  text ".TID" at 3224,-859.5 h60
  text "TID #:" at 3769.5,-859.5 h60
  text "TEXAS INSTRUMENTS" at 904.5,-1064.84 h60
  text ".Print_Time" at 2169,-1064.84 h60
  text ".Print_Date" at 2898,-1064.84 h60
  text "GENERATED    :" at 3767.5,-1064.84 h60
  text ".plot_File_Name" at 5440.5,-1064.84 h60
  text "PLOT NAME =" at 6246,-1064.84 h60
M9 Title Sheet:
  drawing of 57 lines, arcs and shapes, not listed
  text "1" at 739.84,8036.5 h70
  text "2" at 3235.5,8036.5 h70
  text "3" at 5724.84,8036.5 h70
  text "4" at 8231.51,8036.5 h70
  text "5" at 10730.5,8036.5 h70
  text "6" at 13235.5,8036.5 h70
  text "A" at -416.5,6893.5 h70
  text "A" at 14383.5,6893.5 h70
  text "B" at -416.5,4513.5 h70
  text "B" at 14383.5,4513.5 h70
  text "C" at -416.5,2138.5 h70
  text "C" at 14383.5,2138.5 h70
  text "PROJECT TITLE:" at 11343.5,277.5 h45
  text ".PRJ_Title" at 11393.5,144.17 h70
  text "DESIGNED FOR:" at 11343.5,-23.5 h45
  text ".PRJ_Customer" at 11393.5,-163.5 h70
  text "D" at -416.5,-231.5 h70
  text "D" at 14383.5,-231.5 h70
  text "FILE NAME:" at 11343.5,-323.5 h45
  text ".PCB_File_Name_No_Path" at 11393.5,-443.5 h70
  text "Texas Instruments (TI) and/or its licensors do not warrant the accuracy or completeness of this specification" at 6374,-605.34 h45
  text "ENGINEER:" at 11343.5,-613.5 h45
  text "LAYOUT BY:" at 12848.5,-613.5 h45
  text "or any information contained therein. TI and/or its licensors do not warrant that this design will meet" at 6329.01,-718 h45
  text ".PRJ_Engineer" at 11393.5,-768.49 h70
  text ".PCB_Layout" at 12899,-768.49 h70
  text "the specifications, will be suitable for your application or fit for any particular purpose, or will operate in" at 6329.01,-830.67 h45
  text ".Layer_Name" at 577,-858.49 h60
  text "ALTIUM DESIGNER VERSION:" at 12848.5,-923.5 h45
  text "an implementation. TI and/or its licensors do not warrant that the design is production worthy. You should" at 6329.01,-943.33 h45
  text "completely validate and test your design implementation to confirm the system functionality for your application." at 6374,-1056 h45
  text ".print_Scale" at 11393.5,-1056.83 h70
  text ".Application_BuildNumber" at 12899,-1056.83 h70
  text "1" at 739.84,-1263.5 h70
  text "2" at 3235.5,-1263.5 h70
  text "3" at 5724.84,-1263.5 h70
  text "4" at 8231.51,-1263.5 h70
  text "5" at 10730.5,-1263.5 h70
  text "6" at 13235.5,-1263.5 h70
M10 Fab Notes:
  drawing of 185 lines, arcs and shapes, not listed
  text "DESIGN INFORMATION" at 12381.02,5910 h60
  text "MIN. TRACK WIDTH:" at 11736.46,5730 h60
  text "8" at 12832.7,5730 h60
  text "MIL" at 12987.46,5730 h60
  text "MIN. CLEARANCE:" at 11736.46,5598 h60
  text "0.2" at 12772.7,5598 h60
  text "mm" at 12987.46,5598 h60
  text "MIN. VIA PAD SIZE:" at 11736.46,5466 h60
  text "24" at 12802.71,5466 h60
  text "MIL" at 12987.46,5466 h60
  text "0.05mm (2MIL)" at 12431.46,5324.29 h60
  text "MINIMUM ANNULAR RING" at 11407.23,5320 h60
  text "EXTERNAL" at 13139.46,5320 h60
  text "PER" at 11607.23,5202 h60
  text "IPC-D-275 CLASS 2 LEVEL C" at 11827.23,5202 h60
  text "MIL, HOLES" at 13315.46,5089.71 h60
  text "+/-" at 12923,5089 h60
  text "+/-" at 13777,5089 h60
  text "REGISTRATION TOLERANCES:" at 11407.23,5084 h60
  text "METAL" at 12607,5084 h60
  text "5" at 13183.2,5084 h60
  text "3" at 14016.2,5084 h60
  text "MIL" at 14132.46,5084 h60
  text "MATERIAL:" at 11332.46,4874.54 h60
  text "FR-4 High Tg" at 12318.9,4734.21 h60
  text "FR-408" at 11753.46,4725.64 h60
  text "X" at 12165.46,4725.64 h60
  text "OTHER" at 13241.46,4725.64 h60
  text "62 MIL (1.6mm) +/-10%" at 12073.56,4562.92 h60
  text "THICKNESS:" at 11407.23,4558.64 h60
  text "X" at 11945.4,4558.64 h60
  text "OTHER" at 13358.46,4558.64 h60
  text "TOLERANCE:" at 11407.23,4400.64 h60
  text "X" at 12246.53,4400.64 h60
  text "ANSI IPC-6012 TYPE 3 CLASS 2" at 12433.48,4400.64 h60
  text "OTHER +/-" at 12433.46,4244.64 h60
  text "BOW & TWIST:" at 11407.23,4087.64 h60
  text "X" at 12246.53,4087.64 h60
  text "ANSI IPC-6012 TYPE 3 CLASS 2" at 12433.48,4087.64 h60
  text "OTHER +/-" at 12433.46,3929.13 h60
  text "DRILLING:" at 11332.46,3790.64 h60
  text "REFERENCE:" at 11407.23,3673.64 h60
  text "X" at 12055.46,3673.64 h60
  text "AS SHOWN" at 12242.46,3673.64 h60
  text "X" at 12956.46,3673.64 h60
  text "NC_DRILL FILES" at 13093.46,3673.64 h60
  text "PTH MIN COPPER THICKNESS:" at 11407.23,3515.64 h60
  text "X" at 12757.46,3515.64 h60
  text "1MIL" at 12894.46,3515.64 h60
  text "OTHER" at 13391.46,3515.64 h60
  text "BOARD FINISH:" at 11332.46,3356.64 h60
  text "SILKSCREEN:" at 11487.68,3238.64 h60
  text "X" at 12436.46,3238.64 h60
  text "TOP" at 12562.46,3238.64 h60
  text "X" at 12946.46,3238.64 h60
  text "BOTTOM" at 13073.46,3238.64 h60
  text "SILKSCREEN COLOR:" at 11487.68,3071.64 h60
  text "X" at 12435.42,3071.64 h60
  text "WHITE" at 12562.46,3071.64 h60
  text "OTHER" at 13073.46,3071.64 h60
  text "SOLDER RESIST COLOR:" at 11487.68,2901.64 h60
  text "X" at 12055.42,2742.44 h60
  text "GREEN" at 12182.46,2742.44 h60
  text "BLUE" at 12773.46,2742.44 h60
  text "OTHER" at 13311.46,2742.44 h60
  text "IMMERSION GOLD (ENIG)" at 12393.46,2553.92 h60
  text "ENEPIG" at 13731,2550.64 h60
  text "SURFACE FINISH:" at 11332.46,2549.64 h60
  text "X" at 12206.51,2549.64 h60
  text "IMM. TIN/SILVER OR EQUIV" at 11662,2392.64 h60
  text "OTHER" at 13093.46,2392.64 h60
  text "ARRAY/PANEL:" at 11332.46,2213.64 h60
  text "CUT AND TRIM PER MECH LAYER 1" at 12393.46,2209.35 h60
  text "N.C. ROUTE" at 12393.46,2057.64 h60
  text "X" at 13072.46,2057.64 h60
  text "V. SCORE" at 13259.46,2057.64 h60
  text "CERTIFICATION:" at 11332.46,1920.64 h60
  text "MATERIALS AND WORKMANSHIP FOR ALL PCBS" at 12057.46,1920.64 h60
  text "TO MEET OR EXCEED THE REQUIREMENTS OF:" at 12057.46,1822.64 h60
  text "X" at 11683.96,1686.13 h60
  text "ANSI IPC-A-600F CLASS ->" at 11822.96,1686.13 h60
  text "X" at 13462.02,1686.13 h60
  text "2" at 13580.96,1686.14 h60
  text "1" at 13265.96,1684.64 h60
  text "3" at 13934.96,1684.64 h60
  text "X" at 11686.02,1526.64 h60
  text "UL 94V-0" at 11822.96,1526.64 h60
  text "X" at 12498.02,1526.64 h60
  text "RoHS" at 12634.96,1526.64 h60
  text "OTHER" at 13279.36,1526.64 h60
  text "PER ORDER" at 13676.42,1526.64 h60
  text "ADDITIONAL REQUIREMENTS:" at 11332.46,1385.64 h60
  text "MICROSECTION:" at 11407.23,1270.64 h60
  text "YES" at 12312.96,1270.64 h60
  text "REQUIRED" at 13174.46,1114.49 h60
  text "BARE BOARD ELEC. TEST:" at 11407.23,1111.64 h60
  text "NONE" at 12712.96,1111.64 h60
  text "X" at 13047.46,1111.64 h60
  text "PER ORDER" at 13766.46,1111.64 h60
  text "MANUFACTURER'S UL:" at 11407.23,954.64 h60
  text "RAIL" at 12572.96,950.35 h60
  text "METAL" at 13064.77,950.35 h60
  text "X" at 13440,950 h60
  text "SILK" at 13576.46,950.35 h60
  text ".Layer_Name" at 577,-858.49 h60
M11 Gerber Information:
  lines w10: -292,-930.17 6308,-930.17 ; -292,-726.83 6310,-726.83 ; -292,-523.5 -292,-1133.5 3713,-1133.5 6310,-1133.5 6310,-523.5 -291.5,-523.5 -291.5,-1133.5 1284,-1133.5 ; 2173,-1133.5 2173,-523.5 ; 3440,-726.83 3440,-523.5 ; 4280,-726.83 4280,-523.5 ; 4902,-1140 4902,-937.17
  text "ALL ARTWORK VIEWED FROM TOP SIDE" at -228.5,-655.67 h60
  text "BOARD #:" at 2248,-655.67 h60
  text ".PRJ_Number" at 2793.5,-655.67 h60
  text "REV:" at 3638,-655.67 h60
  text ".PCB_Rev" at 3929.5,-655.67 h60
  text "SVN REV:" at 4476,-655.67 h60
  text ".VersionControl_RevNumber" at 4982,-655.67 h60
  text "LAYER NAME =" at -228.5,-858.49 h60
  text "TID #:" at 2248,-859 h60
  text ".TID" at 2793.5,-859 h60
  text "PLOT NAME =" at -228.5,-1064.34 h60
  text ".plot_File_Name" at 577,-1064.34 h60
  text "GENERATED    :" at 2250,-1064.34 h60
  text ".Print_Date" at 3119.5,-1064.34 h60
  text ".Print_Time" at 3848.5,-1064.34 h60
  text "TEXAS INSTRUMENTS" at 5113,-1064.34 h60
M12 Stackup:
  drawing of 191 lines, arcs and shapes, not listed
  text "Layer" at 9790.58,7830 h60
  text "Name" at 10200.49,7830 h60
  text "Material" at 11130.23,7830 h60
  text "Thickness" at 11990,7830 h60
  text "Constant" at 12639.84,7830 h60
  text "Board Layer Stack" at 13209.7,7830 h60
  text "1" at 9790.58,7710 h60
  text "Top Overlay" at 10200.49,7710 h60
  text "2" at 9790.58,7590 h60
  text "Top Solder" at 10200.49,7590 h60
  text "Solder Resist" at 11130.23,7590 h60
  text "0.40mil" at 11990,7590 h60
  text "3.5" at 12639.84,7590 h60
  text "3" at 9790.58,7470 h60
  text "Top Layer" at 10200.49,7470 h60
  text "Copper" at 11130.23,7470 h60
  text "1.40mil" at 11990,7470 h60
  text "4" at 9790.58,7350 h60
  text "Dielectric1" at 10200.49,7350 h60
  text "FR-4" at 11130.23,7350 h60
  text "59.20mil" at 11990,7350 h60
  text "4.8" at 12639.84,7350 h60
  text "5" at 9790.58,7230 h60
  text "Bottom Layer" at 10200.49,7230 h60
  text "Copper" at 11130.23,7230 h60
  text "1.40mil" at 11990,7230 h60
  text "6" at 9790.58,7110 h60
  text "Bottom Solder" at 10200.49,7110 h60
  text "Solder Resist" at 11130.23,7110 h60
  text "0.40mil" at 11990,7110 h60
  text "3.5" at 12639.84,7110 h60
  text "7" at 9790.58,6990 h60
  text "Bottom Overlay" at 10200.49,6990 h60
  text ".Layer_Name" at 577,-858.49 h60
M13 Component Bodies Top:
  text ".Layer_Name" at 577,-858.49 h60
M14 Component Bodies Bottom:
  text ".Layer_Name" at 577,-858.49 h60
M15 Courtyards Top:
  text ".Layer_Name" at 577,-858.49 h60
M16 Courtyards Bottom:
  text ".Layer_Name" at 577,-858.49 h60
Drill Drawing:
  circle w1: c5572.72,3221.04 r14.93
  circle w1: c5572.72,3221.04 r24.89
  circle w1: c5572.72,3071.72 r24.89
  lines w1: 5547.83,1702.96 5597.6,1702.96 5597.6,1752.73 5547.83,1752.73 5547.83,1702.96 ; 5547.83,1877.16 5572.72,1852.28 5597.6,1877.16 5572.72,1902.05 5547.83,1877.16 ; 5547.83,2014.04 5560.27,2014.04 5572.72,2001.6 5585.16,2014.04 5597.6,2014.04 5585.16,2026.48 5597.6,2038.93 5585.16,2038.93 5572.72,2051.37 5560.27,2038.93 5547.83,2038.93 5560.27,2026.48 5547.83,2014.04 ; 5547.83,2150.92 5547.83,2163.36 5560.27,2175.8 5547.83,2188.25 5547.83,2200.69 5560.27,2200.69 5572.72,2188.25 5585.16,2200.69 5597.6,2200.69 5597.6,2188.25 5585.16,2175.8 5597.6,2163.36 5597.6,2150.92 5585.16,2150.92 5572.72,2163.36 5560.27,2150.92 5547.83,2150.92 ; 5547.83,2312.68 5560.27,2312.68 5560.27,2300.24 5585.16,2300.24 5585.16,2312.68 5597.6,2312.68 5597.6,2337.57 5585.16,2337.57 5585.16,2350.01 5560.27,2350.01 5560.27,2337.57 5547.83,2337.57 5547.83,2312.68 ; 5547.83,2449.56 5572.72,2462 5597.6,2449.56 5585.16,2474.44 5597.6,2499.33 5572.72,2486.89 5547.83,2499.33 5560.27,2474.44 5547.83,2449.56 ; 5547.83,2611.32 5560.27,2611.32 5572.72,2598.88 5585.16,2611.32 5597.6,2611.32 5585.16,2623.76 5597.6,2636.21 5585.16,2636.21 5572.72,2648.65 5560.27,2636.21 5547.83,2636.21 5560.27,2623.76 5547.83,2611.32 ; 5547.83,2797.97 5597.6,2797.97 5572.72,2748.2 5547.83,2797.97 ; 5547.83,2947.29 5597.6,2947.29 5572.72,2897.52 5547.83,2947.29 ; 5557.78,1712.91 5587.65,1712.91 5587.65,1742.77 5557.78,1742.77 5557.78,1712.91 ; 5557.78,2019.02 5565.25,2019.02 5572.72,2011.55 5580.18,2019.02 5587.65,2019.02 5580.18,2026.48 5587.65,2033.95 5580.18,2033.95 5572.72,2041.41 5565.25,2033.95 5557.78,2033.95 5565.25,2026.48 5557.78,2019.02 ; 5557.78,2788.01 5587.65,2788.01 5572.72,2758.15 5557.78,2788.01
  lines w12: 5480,1658.16 7598.02,1658.16 ; 5480,3300.68 7598.02,3300.68 ; 5850.36,1508.84 5850.36,3450 ; 6207.36,1508.84 6207.36,3450 ; 6868.93,1508.84 6868.93,3450 ; 7153.07,1508.84 7153.07,3450 ; 5480,1508.84 7598.02,1508.84 7598.02,3450 5480,3450 5480,1508.84
  text "Symbol" at 5569.59,3345.48 h72
  text "Quantity" at 5895.16,3345.48 h72
  text "Finished Hole Size" at 6252.16,3345.48 h72
  text "Plated" at 6913.72,3345.48 h72
  text "Hole Type" at 7197.86,3345.48 h72
  text "56" at 5895.16,3196.16 h60
  text "16.00mil (0.406mm)" at 6252.16,3196.16 h60
  text "PTH" at 6913.72,3196.16 h60
  text "Round" at 7197.86,3196.16 h60
  text "12" at 5895.16,3046.84 h60
  text "33.46mil (0.850mm)" at 6252.16,3046.84 h60
  text "PTH" at 6913.72,3046.84 h60
  text "Round" at 7197.86,3046.84 h60
  text "8" at 5895.16,2897.52 h60
  text "35.43mil (0.900mm)" at 6252.16,2897.52 h60
  text "PTH" at 6913.72,2897.52 h60
  text "Round" at 7197.86,2897.52 h60
  text "13" at 5895.16,2748.2 h60
  text "40.00mil (1.016mm)" at 6252.16,2748.2 h60
  text "PTH" at 6913.72,2748.2 h60
  text "Round" at 7197.86,2748.2 h60
  text "9" at 5895.16,2598.88 h60
  text "51.18mil (1.300mm)" at 6252.16,2598.88 h60
  text "PTH" at 6913.72,2598.88 h60
  text "Round" at 7197.86,2598.88 h60
  text "2" at 5895.16,2449.56 h60
  text "78.74mil (2.000mm)" at 6252.16,2449.56 h60
  text "PTH" at 6913.72,2449.56 h60
  text "Round" at 7197.86,2449.56 h60
  text "4" at 5895.16,2300.24 h60
  text "110.24mil (2.800mm)" at 6252.16,2300.24 h60
  text "PTH" at 6913.72,2300.24 h60
  text "Round" at 7197.86,2300.24 h60
  text "2" at 5895.16,2150.92 h60
  text "153.54mil (3.900mm)" at 6252.16,2150.92 h60
  text "PTH" at 6913.72,2150.92 h60
  text "Round" at 7197.86,2150.92 h60
  text "2" at 5895.16,2001.6 h60
  text "188.00mil (4.775mm)" at 6252.16,2001.6 h60
  text "PTH" at 6913.72,2001.6 h60
  text "Round" at 7197.86,2001.6 h60
  text "1" at 5895.16,1852.28 h60
  text "78.74mil (2.000mm)" at 6252.16,1852.28 h60
  text "PTH" at 6913.72,1852.28 h60
  text "Slot" at 7197.86,1852.28 h60
  text "1" at 5895.16,1702.96 h60
  text "157.48mil (4.000mm)" at 6252.16,1702.96 h60
  text "PTH" at 6913.72,1702.96 h60
  text "Slot" at 7197.86,1702.96 h60
  text "110 Total" at 5895.16,1553.64 h60
  text ".Layer_Name" at 577,-858.49 h60

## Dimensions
0,0 to 4950,0 on M2 Board Dimensions
0,0 to 0,3450 on M2 Board Dimensions
0,-400 to 1000,-400 on M2 Board Dimensions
